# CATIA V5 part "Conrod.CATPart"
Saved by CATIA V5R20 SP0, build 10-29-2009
Part number: Conrod
Material "Steel": density 7860 kg/m3, Young's modulus 2e+11 Pa, Poisson ratio 0.266, thermal expansion 1.17e-05 1/K
Material "Steel": density 7860 kg/m3, Young's modulus 2e+11 Pa, Poisson ratio 0.266, thermal expansion 1.17e-05 1/K
Bounding box of the stored display mesh (mm): x 0 to 16, y -39.999 to 39.999, z -189.99 to 24.99
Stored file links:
  E:\Ehsan\Amoozesh\CATIA\CATIA Course\Basic\Exercises\Assembly\12\Conrod.CATPart
  D:\CATIA V5R20\B20\intel_a\startup\materials\Catalog.CATMaterial
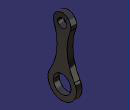
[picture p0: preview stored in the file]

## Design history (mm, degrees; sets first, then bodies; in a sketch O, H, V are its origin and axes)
Body1 (main body), material "Steel"
  Sketch1 on yz-plane, origin (0, 0, 0), H (0, 1, 0), V (0, 0, 1)
    circle A1 centre (0, 0) radius 12.5
    arc A2 centre (0, 0) radius 25 from (23.4187, -8.75) to (-23.4187, -8.75) ccw
    circle A3 centre (0, -150) radius 25
    arc A4 centre (0, -150) radius 40 from (-34.3475, -129.5) to (34.3475, -129.5) ccw
    arc A5 centre (154.5637, -57.75) radius 140 from (23.4187, -8.75) to (34.3475, -129.5) ccw
    arc A6 centre (-154.5637, -57.75) radius 140 from (-23.4187, -8.75) to (-34.3475, -129.5) cw
  Pad1: profile Sketch1, direction (1, 0, 0), length 16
